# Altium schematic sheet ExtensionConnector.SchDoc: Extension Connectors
size A4; Date: Not used; ApprovedBy: Not used; CheckedBy: Not used; Author: Not used; CompanyName: STMicroelectronics; DrawnBy: Not used; Engineer: Not used; Organization: Not used; Address1: Not used; Address2: Not used; Address3: Not used; Address4: Not used; DocumentNumber: Not used; Revision: Not used; SheetNumber: 19; SheetTotal: 23
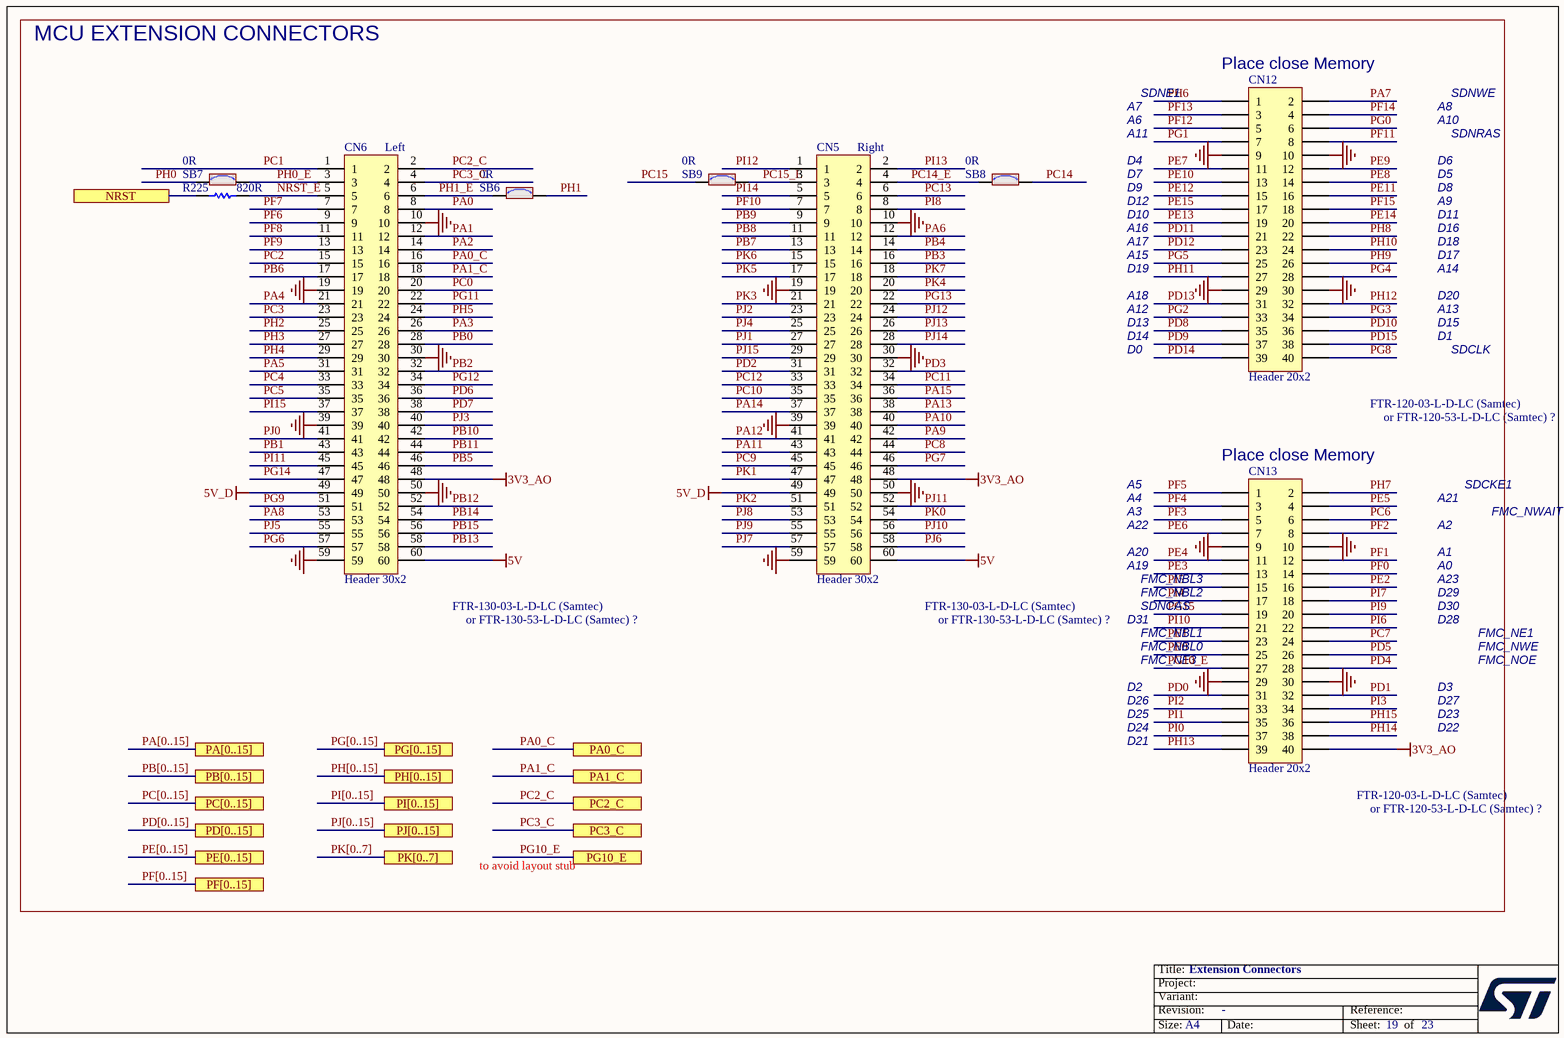
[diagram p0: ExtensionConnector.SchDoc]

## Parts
CN5  Header 30x2  [CON_SAMTEC_FTR-130-53-L-D-LC]
CN6  Header 30x2  [CON_SAMTEC_FTR-130-53-L-D-LC]
CN12  Header 20x2  [CON_SAMTEC_FTR-120-53-L-D-LC]
CN13  Header 20x2  [CON_SAMTEC_FTR-120-53-L-D-LC]
R225  value 820R  [R0603]  (hidden comment: Resistor)
SB6  value 0R  [SOLDER-BRIDGE_R0603-0R]  (hidden comment: SB_ON)
SB7  value 0R  [SOLDER-BRIDGE_R0603-0R]  (hidden comment: SB_ON)
SB8  value 0R  [SOLDER-BRIDGE_R0603-0R]  (hidden comment: SB_ON)
SB9  value 0R  [SOLDER-BRIDGE_R0603-0R]  (hidden comment: SB_ON)

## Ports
NRST, PA0_C, PA1_C, PA[0..15], PB[0..15], PC2_C, PC3_C, PC[0..15], PD[0..15], PE[0..15], PF[0..15], PG10_E, PG[0..15], PH[0..15], PI[0..15], PJ[0..15], PK[0..7]

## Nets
3V3_AO: CN5.48 CN6.48 CN13.40
5V: CN5.60 CN6.60
5V_D: CN5.49 CN6.49
GND: CN5.10 CN5.19 CN5.30 CN5.39 CN5.50 CN5.59 CN6.10 CN6.19 CN6.30 CN6.39 CN6.50 CN6.59 CN12.9 CN12.10 CN12.29 CN12.30 CN13.9 CN13.10 CN13.29 CN13.30
NRST: R225.1 ; port NRST
NRST_E: CN6.5 R225.2
PA0: CN6.8
PA0_C: CN6.16 ; port PA0_C
PA1: CN6.12
PA1_C: CN6.18 ; port PA1_C
PA2: CN6.14
PA3: CN6.26
PA4: CN6.21
PA5: CN6.31
PA6: CN5.12
PA7: CN12.2
PA8: CN6.53
PA9: CN5.42
PA10: CN5.40
PA11: CN5.43
PA12: CN5.41
PA13: CN5.38
PA14: CN5.37
PA15: CN5.36
PB0: CN6.28
PB1: CN6.43
PB2: CN6.32
PB3: CN5.16
PB4: CN5.14
PB5: CN6.46
PB6: CN6.17
PB7: CN5.13
PB8: CN5.11
PB9: CN5.9
PB10: CN6.42
PB11: CN6.44
PB12: CN6.52
PB13: CN6.58
PB14: CN6.54
PB15: CN6.56
PC0: CN6.20
PC1: CN6.1
PC2: CN6.15
PC2_C: CN6.2 ; port PC2_C
PC3: CN6.23
PC3_C: CN6.4 ; port PC3_C
PC4: CN6.33
PC5: CN6.35
PC6: CN13.6
PC7: CN13.24
PC8: CN5.44
PC9: CN5.45
PC10: CN5.35
PC11: CN5.34
PC12: CN5.33
PC13: CN5.6
PC14: SB8.2
PC14_E: CN5.4 SB8.1
PC15: SB9.1
PC15_E: CN5.3 SB9.2
PD0: CN13.31
PD1: CN13.32
PD2: CN5.31
PD3: CN5.32
PD4: CN13.28
PD5: CN13.26
PD6: CN6.36
PD7: CN6.38
PD8: CN12.35
PD9: CN12.37
PD10: CN12.36
PD11: CN12.21
PD12: CN12.23
PD13: CN12.31
PD14: CN12.39
PD15: CN12.38
PE0: CN13.25
PE1: CN13.23
PE2: CN13.16
PE3: CN13.13
PE4: CN13.11
PE5: CN13.4
PE6: CN13.7
PE7: CN12.11
PE8: CN12.14
PE9: CN12.12
PE10: CN12.13
PE11: CN12.16
PE12: CN12.15
PE13: CN12.19
PE14: CN12.20
PE15: CN12.17
PF0: CN13.14
PF1: CN13.12
PF2: CN13.8
PF3: CN13.5
PF4: CN13.3
PF5: CN13.1
PF6: CN6.9
PF7: CN6.7
PF8: CN6.11
PF9: CN6.13
PF10: CN5.7
PF11: CN12.8
PF12: CN12.5
PF13: CN12.3
PF14: CN12.4
PF15: CN12.18
PG0: CN12.6
PG1: CN12.7
PG2: CN12.33
PG3: CN12.34
PG4: CN12.28
PG5: CN12.25
PG6: CN6.57
PG7: CN5.46
PG8: CN12.40
PG9: CN6.51
PG10_E: CN13.27 ; port PG10_E
PG11: CN6.22
PG12: CN6.34
PG13: CN5.22
PG14: CN6.47
PG15: CN13.19
PH0: SB7.1
PH0_E: CN6.3 SB7.2
PH1: SB6.2
PH1_E: CN6.6 SB6.1
PH2: CN6.25
PH3: CN6.27
PH4: CN6.29
PH5: CN6.24
PH6: CN12.1
PH7: CN13.2
PH8: CN12.22
PH9: CN12.26
PH10: CN12.24
PH11: CN12.27
PH12: CN12.32
PH13: CN13.39
PH14: CN13.38
PH15: CN13.36
PI0: CN13.37
PI1: CN13.35
PI2: CN13.33
PI3: CN13.34
PI4: CN13.17
PI5: CN13.15
PI6: CN13.22
PI7: CN13.18
PI8: CN5.8
PI9: CN13.20
PI10: CN13.21
PI11: CN6.45
PI12: CN5.1
PI13: CN5.2
PI14: CN5.5
PI15: CN6.37
PJ0: CN6.41
PJ1: CN5.27
PJ2: CN5.23
PJ3: CN6.40
PJ4: CN5.25
PJ5: CN6.55
PJ6: CN5.58
PJ7: CN5.57
PJ8: CN5.53
PJ9: CN5.55
PJ10: CN5.56
PJ11: CN5.52
PJ12: CN5.24
PJ13: CN5.26
PJ14: CN5.28
PJ15: CN5.29
PK0: CN5.54
PK1: CN5.47
PK2: CN5.51
PK3: CN5.21
PK4: CN5.20
PK5: CN5.17
PK6: CN5.15
PK7: CN5.18

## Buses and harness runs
bus PA[0..15] = port PA[0..15]
bus PB[0..15] = port PB[0..15]
bus PC[0..15] = port PC[0..15]
bus PD[0..15] = port PD[0..15]
bus PE[0..15] = port PE[0..15]
bus PF[0..15] = port PF[0..15]
bus PG[0..15] = port PG[0..15]
bus PH[0..15] = port PH[0..15]
bus PI[0..15] = port PI[0..15]
bus PJ[0..15] = port PJ[0..15]
bus PK[0..7] = port PK[0..7]

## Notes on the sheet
- MCU EXTENSION CONNECTORS
- A7
- SDNE1
- (near CN12) Place close Memory
- A8
- SDNWE
- (near CN6) Left
- (near CN5) Right
- D4
- D7
- A6
- A11
- D5
- D6
- A10
- SDNRAS
- A16
- A17
- D9
- D10
- D12
- D8
- D11
- A9
- D16
- D18
- A18
- A12
- A15
- D19
- A13
- A14
- D17
- D20
- D13
- D14
- D0
- D15
- D1
- SDCLK
- (near CN12) FTR-120-03-L-D-LC (Samtec)
- or FTR-120-53-L-D-LC (Samtec) ?
- A3
- A4
- A5
- (near CN13) Place close Memory
- A21
- SDCKE1
- FMC_NWAIT
- A19
- A20
- A22
- FMC_NBL3
- A23
- A0
- A1
- A2
- (near CN6) FTR-130-03-L-D-LC (Samtec)
- or FTR-130-53-L-D-LC (Samtec) ?
- (near CN5) FTR-130-03-L-D-LC (Samtec)
- D31
- FMC_NBL0
- FMC_NBL1
- SDNCAS
- FMC_NBL2
- D28
- D29
- D30
- FMC_NWE
- FMC_NE1
- D2
- D25
- D26
- FMC_NE3
- D3
- D23
- D27
- FMC_NOE
- D21
- D24
- D22
- (near CN13) FTR-120-03-L-D-LC (Samtec)
- to avoid layout stub

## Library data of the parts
CN5 CN6 = MCD-00576: Header 30x2, 1.27mm, VR, CMS, Height 7.24mm; Part_Type: Connector; Manufacturer_Part_Number: FTR-130-53-L-D-LC; Manufacturer: SAMTEC; Alternate_Manufacturer_Part_Number: P1039-2*30MGF-089-1A; Alternate_Manufacturer: JIUBABA; Part_Preference: Recommended; Provided_By: SUBCO; Component_Country_Of_Origin: China, Costa Rica, Malaysia, USA, Vietnam; ID: 3170; ShowFields: YES
CN12 CN13 = MCD-00578: Header 20x2, 1.27mm, VR, CMS, Height 7.24mm; Part_Type: Connector; Manufacturer_Part_Number: FTR-120-53-L-D-LC; Manufacturer: SAMTEC; Alternate_Manufacturer_Part_Number: P1039-2*20MGF-089-1A; Alternate_Manufacturer: JIUBABA; Part_Preference: Recommended; Provided_By: SUBCO; Component_Country_Of_Origin: China, Costa Rica, Malaysia, USA, Vietnam; ID: 3165; ShowFields: YES
R225 = MCD-00528: Resistor,820R,0603,1%,1/10W; Manufacturer_Part_Number: RC0603FR-07820RL; Manufacturer: YAGEO; BMS_Part_Number: 9129759; Part_Preference: Recommended; Provided_By: SUBCO; ECCN_US: EAR99; ECCN_EU: NEC; Component_Country_Of_Origin: China; ID: 3218; ShowFields: YES
SB6-SB9 = MCD-00071: Solder Bridge ON; Part_Type: Resistor; Manufacturer_Part_Number: RC0603JR-070RL; Manufacturer: YAGEO; Manufacturer_HQ_COO: Unknown; Part_Preference: Recommended; Provided_By: SUBCO; Component_Country_Of_Origin: China; ID: 2521; Order_Code_RS: 199-5647; ShowFields: YES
